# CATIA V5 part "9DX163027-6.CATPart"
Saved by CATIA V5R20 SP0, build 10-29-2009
Part number: 9DX163027-6
Revision: ANY
Definition: UNKNOWN
Nomenclature: 9DX163027-6
Source: Unknown
Bounding box of the stored display mesh (mm): x -16.827 to 16.827, y 0 to 23, z -17 to 17
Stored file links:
  C:\Users\Utente\Desktop\IO LAVORO\3D X SITO CF\CUMSA\3D files DX\DX 163027\9DX163027-6.CATPart
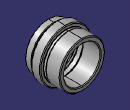
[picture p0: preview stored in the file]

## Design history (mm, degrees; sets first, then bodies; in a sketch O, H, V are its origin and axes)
Body1 "Redondeo1" (main body)
  Solid1: solid without history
